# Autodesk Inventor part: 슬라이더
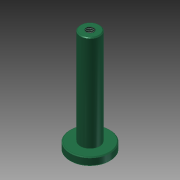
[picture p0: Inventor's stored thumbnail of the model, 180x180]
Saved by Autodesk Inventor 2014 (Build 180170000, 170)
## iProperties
Created: 2016-02
Part Number: 슬라이더
Material: 스테인리스강
Document SubType Name: Modeling
Designer: mduedu
Density: 8.08 g/cm^3
Mass: 72.5507 g
Surface Area: 37.669 cm^2
Volume: 8.97904 cm^3
Appearance: 매끄러움 - 짙은 바다 녹색
Author: mduedu
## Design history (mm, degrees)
sketch "스케치1"
  geometry: C1 r 12.5 at (0, 0); 1 further point
  constraints: 1 centre point, 1 coincident
  dimensions: "d0" = 25 diameter of C1
extrude "돌출1" new body sketch "스케치1" distance "d1" = 5; taper "d2" = 0 deg
sketch "스케치2"
  geometry: C1 r 6 at (0, 0); 1 further point
  constraints: 1 centre point, 1 coincident
  dimensions: "d3" = 12 diameter of C1
extrude "돌출2" join sketch "스케치2" distance "d4" = 60; taper "d5" = 0 deg
chamfer "모따기1" distance "d6" = 0.5; stored, may be unused: second distance "d7" = 2, angle "d8" = 45 deg
hole "구멍1" diameter "d11" = 4.917; stored, may be unused: countersink angle "d15" = 90 deg, drill point angle "d17" = 118 deg; dims "d9" = 10, "d10" = 10, "d12" = 10, "d13" = 4, "d14" = 2, "d16" = 12
chamfer "모따기2" distance "d18" = 0.5; stored, may be unused: second distance "d19" = 2, angle "d20" = 45 deg
sketch "스케치3"
  geometry: L1 (-12.5, 4.5)-(-12, 5) reference; L2 (-12, 5)-(-6, 5) reference; L3 (-6, 5)-(-6, 64.5) reference; L4 (-6, 64.5)-(-5.5, 65) reference; L5 (-5.5, 65)-(-2.458, 65) reference; L6 (-2.458, 65)-(-2.458, 53) reference; L7 (-2.458, 53)-(0, 51.523) reference; L8 (0, 51.523)-(2.458, 53) reference; L9 (2.458, 53)-(2.458, 65) reference; L10 (2.458, 65)-(5.5, 65) reference; L11 (5.5, 65)-(6, 64.5) reference; L12 (6, 64.5)-(6, 5) reference; L13 (6, 5)-(12, 5) reference; L14 (12, 5)-(12.5, 4.5) reference; L15 (12.5, 4.5)-(12.5, 0.5) reference; L16 (12.5, 0.5)-(12, 0) reference; L17 (12, 0)-(-12, 0) reference; L18 (-12, 0)-(-12.5, 0.5) reference; L19 (-12.5, 0.5)-(-12.5, 4.5) reference; 1 further point
  node "절단 모서리 투영1"
node "솔리드1"
